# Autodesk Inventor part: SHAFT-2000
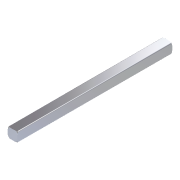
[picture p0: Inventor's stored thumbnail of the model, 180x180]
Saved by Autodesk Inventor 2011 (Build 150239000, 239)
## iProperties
Created: 2007-08
Part Number: SHAFT-2000
Material: Stainless Steel
Document SubType Name: Modeling
Density: 8.08 g/cm^3
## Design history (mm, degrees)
feature "Base1"
workaxis "Work Axis1"
  workplane "Work Plane1"
  workplane "Work Plane2"
workaxis "Work Axis2"
  workplane "Work Plane3"
  workplane "Work Plane4"
body "Solid1"
